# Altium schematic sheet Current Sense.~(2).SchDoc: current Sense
size 431 x 279 mm; Date: Not shown in title block; ApprovedBy: Not shown in title block; CheckedBy: Not shown in title block; Author: Not shown in title block; CompanyName: Not shown in title block; Engineer: Not shown in title block; Organization: Not shown in title block; Address1: Not shown in title block; Address2: Not shown in title block; Address3: Not shown in title block; Address4: Not shown in title block; DocumentNumber: 3; Revision: Use project parameter SCH_Rev; SheetNumber: 3; SheetTotal: 7; PageSetup: Record=PageOptions|CenterHorizontal=True|CenterVertical=True|PrintScale=1.00|XCorrection=1.00|YCorrection=1.00|PrintKind=0|BorderSize=5000000|LeftOffset=0|BottomOffset=0|Orientation=2|PaperLength=1000|PaperWidth=1000|Scale=100|PaperSource=15|PrintQuality=600|MediaType=1|DitherType=10|PaperKind=Letter|PrintScaleMode=1
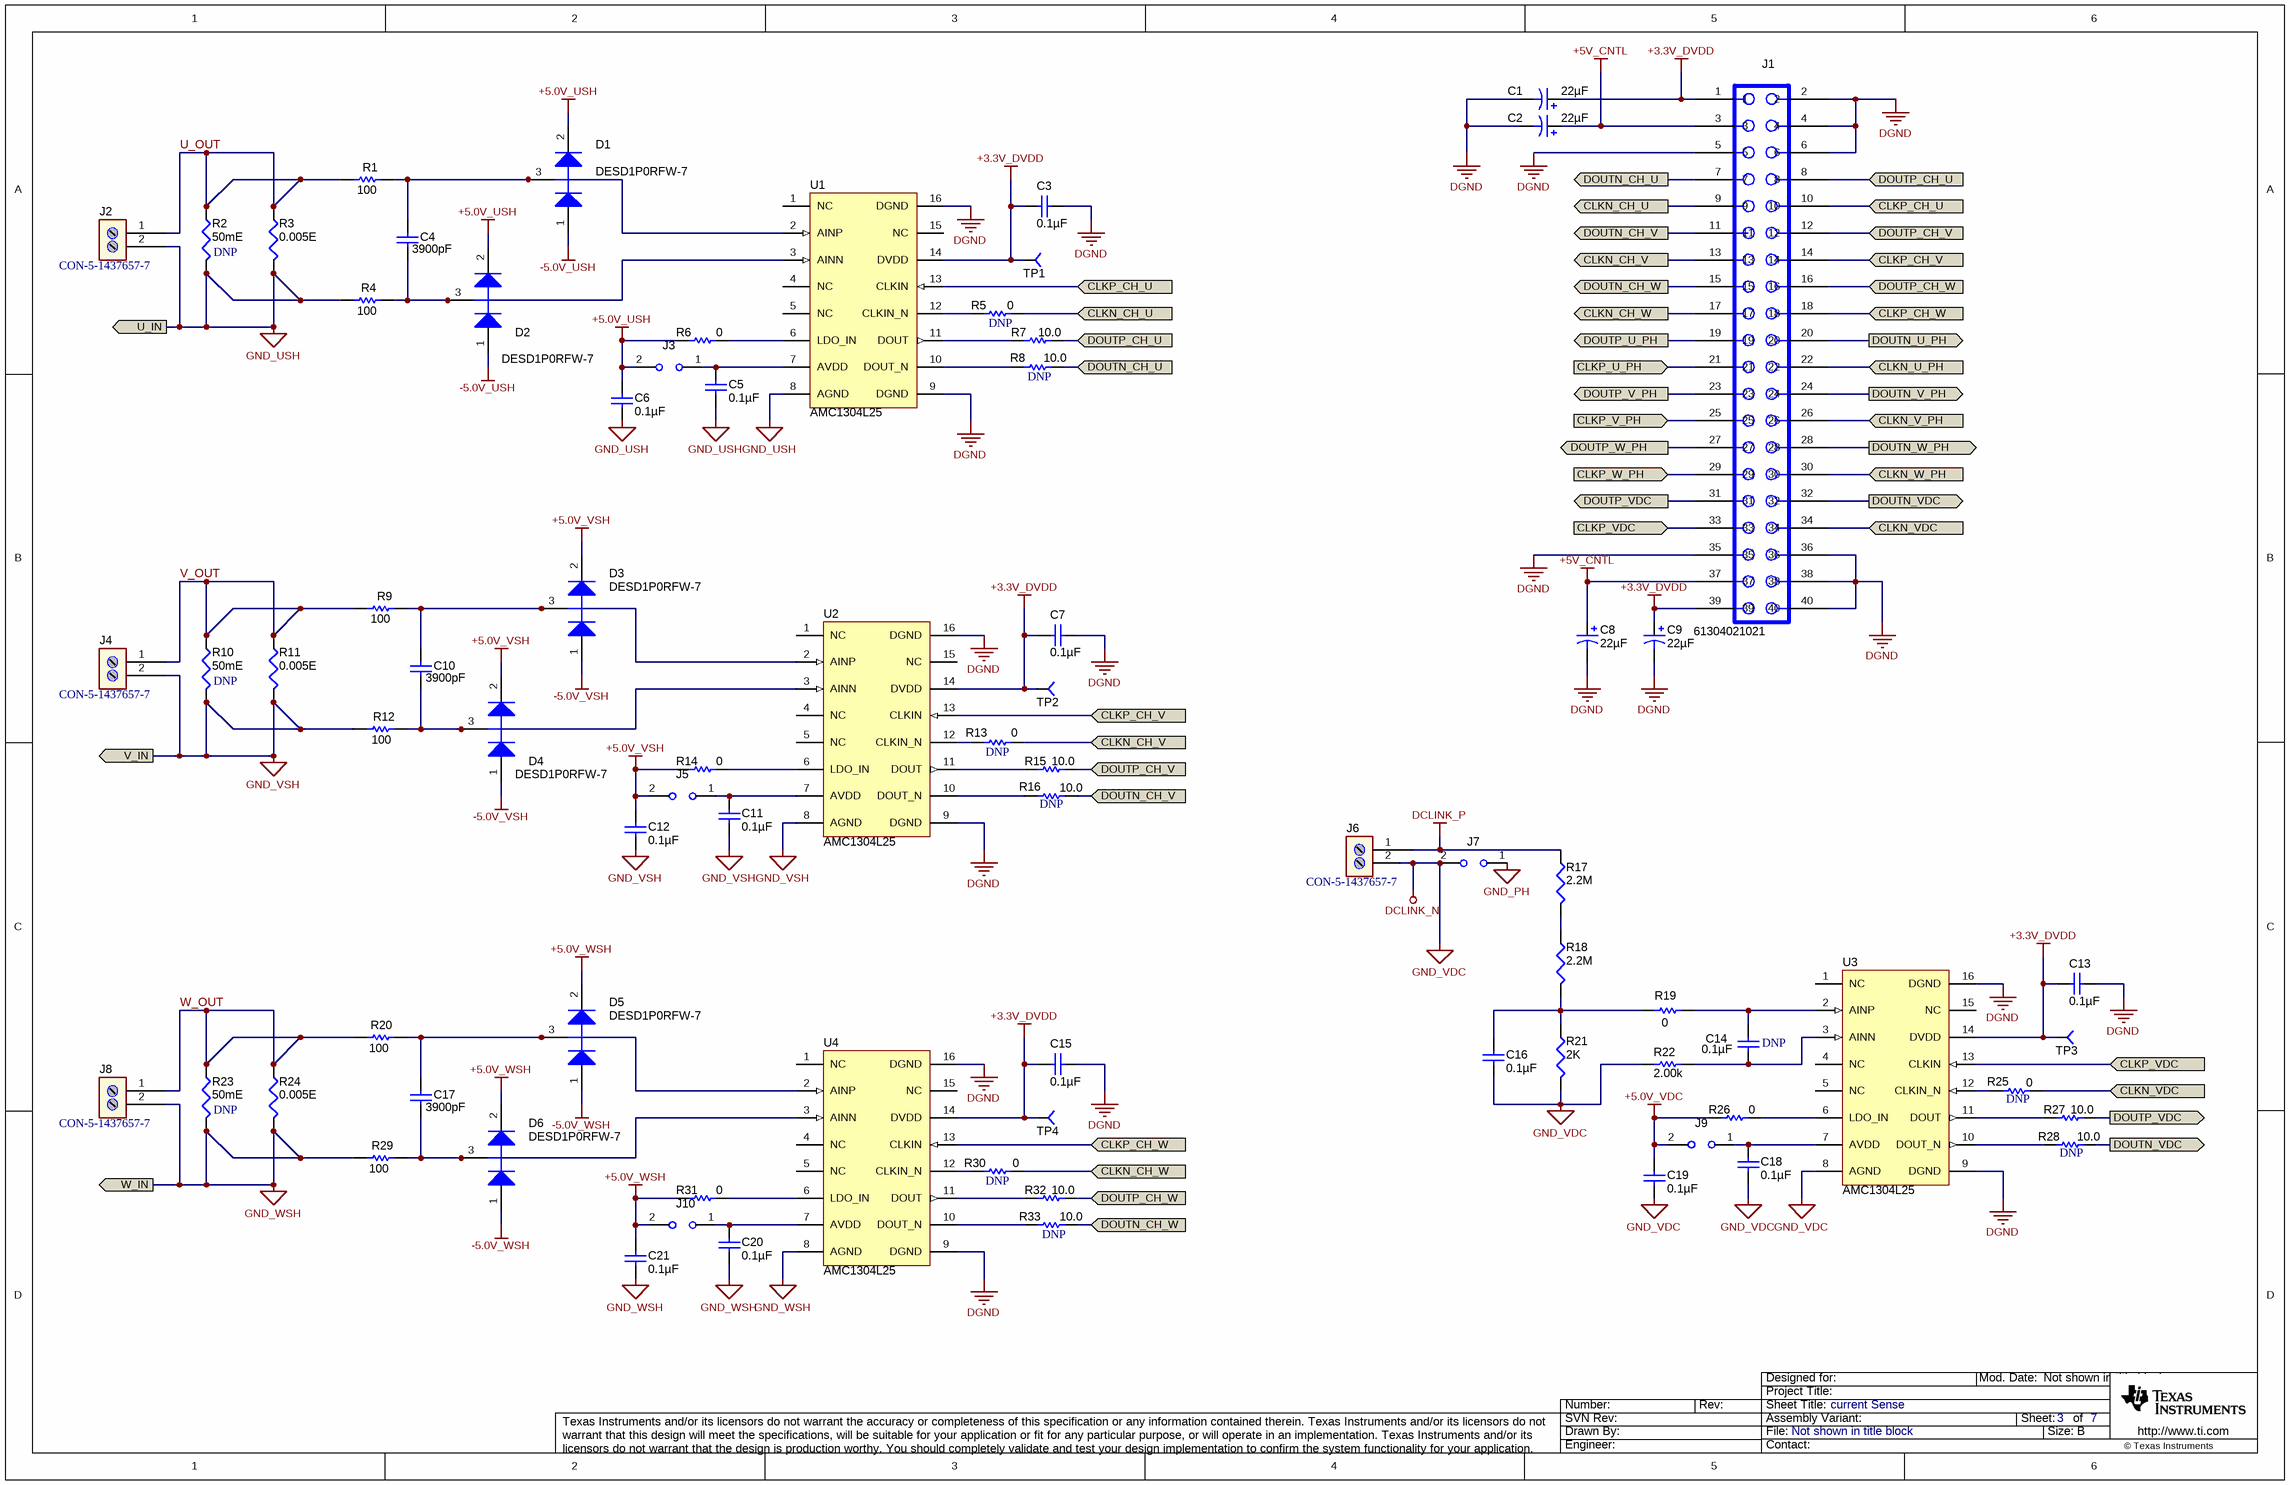
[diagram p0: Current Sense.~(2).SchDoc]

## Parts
C1  ValueDisplayed: 22µF  [SM_RADIAL_5MM]  (hidden comment: UUD1E220MCL1GS)
C2  ValueDisplayed: 22µF  [SM_RADIAL_5MM]  (hidden comment: UUD1E220MCL1GS)
C3  ValueDisplayed: 0.1µF  [0603]
C4  ValueDisplayed: 3900pF  [0603]  (hidden comment: C1608C0G1E392J)
C5  ValueDisplayed: 0.1µF  [0603]
C6  ValueDisplayed: 0.1µF  [0603]
C7  ValueDisplayed: 0.1µF  [0603]
C8  ValueDisplayed: 22µF  [SM_RADIAL_5MM]  (hidden comment: UUD1E220MCL1GS)
C9  ValueDisplayed: 22µF  [SM_RADIAL_5MM]  (hidden comment: UUD1E220MCL1GS)
C10  ValueDisplayed: 3900pF  [0603]  (hidden comment: C1608C0G1E392J)
C11  ValueDisplayed: 0.1µF  [0603]
C12  ValueDisplayed: 0.1µF  [0603]
C13  ValueDisplayed: 0.1µF  [0603]
C14  ValueDisplayed: 0.1µF  Not mounted: DNP  [0603]
C15  ValueDisplayed: 0.1µF  [0603]
C16  ValueDisplayed: 0.1µF  [0603]
C17  ValueDisplayed: 3900pF  [0603]  (hidden comment: C1608C0G1E392J)
C18  ValueDisplayed: 0.1µF  [0603]
C19  ValueDisplayed: 0.1µF  [0603]
C20  ValueDisplayed: 0.1µF  [0603]
C21  ValueDisplayed: 0.1µF  [0603]
D1  value DESD1P0RFW-7  [SOT-323]
D2  value DESD1P0RFW-7  [SOT-323]
D3  DESD1P0RFW-7  [SOT-323]
D4  DESD1P0RFW-7  [SOT-323]
D5  DESD1P0RFW-7  [SOT-323]
D6  DESD1P0RFW-7  [SOT-323]
J1  61304021021  [CONN_61304021021]
J2  CON-5-1437657-7  [5-1437657-7]
J3  (no value)  [HDR100_1X2]
J4  CON-5-1437657-7  [5-1437657-7]
J5  (no value)  [HDR100_1X2]
J6  CON-5-1437657-7  [5-1437657-7]
J7  (no value)  [HDR100_1X2]
J8  CON-5-1437657-7  [5-1437657-7]
J9  (no value)  [HDR100_1X2]
J10  (no value)  [HDR100_1X2]
R1  value 100  [0603]  (hidden comment: RC0603FR-07100RL)
R2  value 50mE  Not mounted: DNP  [R_TO-247]  (hidden comment: PBH-R050-F1-0.5)
R3  value 0.005E  [PWR4413D-R050F]  (hidden comment: OAR5R005FLF)
R4  value 100  [0603]  (hidden comment: RC0603FR-07100RL)
R5  value 0  Not mounted: DNP  [0603]
R6  value 0  [0603]
R7  value 10.0  [0603]
R8  value 10.0  Not mounted: DNP  [0603]
R9  value 100  [0603]  (hidden comment: RC0603FR-07100RL)
R10  value 50mE  Not mounted: DNP  [R_TO-247]  (hidden comment: PBH-R050-F1-0.5)
R11  value 0.005E  [PWR4413D-R050F]  (hidden comment: OAR5R005FLF)
R12  value 100  [0603]  (hidden comment: RC0603FR-07100RL)
R13  value 0  Not mounted: DNP  [0603]
R14  value 0  [0603]
R15  value 10.0  [0603]
R16  value 10.0  Not mounted: DNP  [0603]
R17  value 2.2M  [1210M]
R18  value 2.2M  [1210M]
R19  value 0  [0603]  (hidden comment: CRCW06030000Z0EA)
R20  value 100  [0603]  (hidden comment: RC0603FR-07100RL)
R21  value 2K  [1210M]
R22  value 2.00k  [0603]  (hidden comment: RT0603DRE072KL)
R23  value 50mE  Not mounted: DNP  [R_TO-247]  (hidden comment: PBH-R050-F1-0.5)
R24  value 0.005E  [PWR4413D-R050F]  (hidden comment: OAR5R005FLF)
R25  value 0  Not mounted: DNP  [0603]
R26  value 0  [0603]
R27  value 10.0  [0603]
R28  value 10.0  Not mounted: DNP  [0603]
R29  value 100  [0603]  (hidden comment: RC0603FR-07100RL)
R30  value 0  Not mounted: DNP  [0603]
R31  value 0  [0603]
R32  value 10.0  [0603]
R33  value 10.0  Not mounted: DNP  [0603]
TP1  (no value)  [TP-040_RND]
TP2  (no value)  [TP-040_RND]
TP3  (no value)  [TP-040_RND]
TP4  (no value)  [TP-040_RND]
U1  AMC1304L25  [DW0016A_N]
U2  AMC1304L25  [DW0016A_N]
U3  AMC1304L25  [DW0016A_N]
U4  AMC1304L25  [DW0016A_N]

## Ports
CLKN_CH_U, CLKN_CH_V, CLKN_CH_W, CLKN_U_PH (in), CLKN_V_PH (in), CLKN_VDC (in), CLKN_W_PH (in), CLKP_CH_U, CLKP_CH_V, CLKP_CH_W, CLKP_U_PH (in), CLKP_V_PH (in), CLKP_VDC (in), CLKP_W_PH (in), DOUTN_CH_U, DOUTN_CH_V, DOUTN_CH_W, DOUTN_U_PH (out), DOUTN_V_PH (out), DOUTN_VDC (out), DOUTN_W_PH (out), DOUTP_CH_U, DOUTP_CH_V, DOUTP_CH_W, DOUTP_U_PH (out), DOUTP_V_PH (out), DOUTP_VDC (out), DOUTP_W_PH (out), U_IN (out), V_IN (out), W_IN (out)

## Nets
+3.3V_DVDD: C1.1(+) C3.2 C7.2 C9.1(+) C13.2 C15.2 J1.1 J1.39 TP1.1 TP2.1 TP3.1 TP4.1 U1.14(DVDD) U2.14(DVDD) U3.14(DVDD) U4.14(DVDD)
+5.0V_USH: C6.1 D1.2(K) D2.2(K) J3.2 R6.1
+5.0V_VDC: C19.1 J9.2 R26.1
+5.0V_VSH: C12.1 D3.2(K) D4.2(K) J5.2 R14.1
+5.0V_WSH: C21.1 D5.2(K) D6.2(K) J10.2 R31.1
+5V_CNTL: C2.1(+) C8.1(+) J1.3 J1.37
-5.0V_USH: D1.1(A) D2.1(A)
-5.0V_VSH: D3.1(A) D4.1(A)
-5.0V_WSH: D5.1(A) D6.1(A)
DCLINK_N: C16.1 C18.2 C19.2 J6.2 J7.2 R21.2 R22.1 U3.8(AGND)  [also labelled GND_VDC]
DCLINK_P: J6.1 R17.1
DGND: C1.2(-) C2.2(-) C3.1 C7.1 C8.2(-) C9.2(-) C13.1 C15.1 J1.2 J1.4 J1.5 J1.6 J1.35 J1.36 J1.38 J1.40 U1.9(DGND) U1.16(DGND) U2.9(DGND) U2.16(DGND) U3.9(DGND) U3.16(DGND) U4.9(DGND) U4.16(DGND)
GND_PH: J7.1
GND_USH: C5.2 C6.2 J2.2 R2.2 R3.2 R4.1 U1.8(AGND) ; port U_IN
GND_VSH: C11.2 C12.2 J4.2 R10.2 R11.2 R12.1 U2.8(AGND) ; port V_IN
GND_WSH: C20.2 C21.2 J8.2 R23.2 R24.2 R29.1 U4.8(AGND) ; port W_IN
CLKN_CH_U: J1.9 R5.2 ; port CLKN_CH_U
CLKN_CH_V: J1.13 R13.2 ; port CLKN_CH_V
CLKN_CH_W: J1.17 R30.2 ; port CLKN_CH_W
CLKN_U_PH: J1.22 ; port CLKN_U_PH
CLKN_V_PH: J1.26 ; port CLKN_V_PH
CLKN_VDC: J1.34 R25.2 ; port CLKN_VDC
CLKN_W_PH: J1.30 ; port CLKN_W_PH
CLKP_CH_U: J1.10 U1.13(CLKIN) ; port CLKP_CH_U
CLKP_CH_V: J1.14 U2.13(CLKIN) ; port CLKP_CH_V
CLKP_CH_W: J1.18 U4.13(CLKIN) ; port CLKP_CH_W
CLKP_U_PH: J1.21 ; port CLKP_U_PH
CLKP_V_PH: J1.25 ; port CLKP_V_PH
CLKP_VDC: J1.33 U3.13(CLKIN) ; port CLKP_VDC
CLKP_W_PH: J1.29 ; port CLKP_W_PH
DOUTN_CH_U: J1.7 R8.2 ; port DOUTN_CH_U
DOUTN_CH_V: J1.11 R16.2 ; port DOUTN_CH_V
DOUTN_CH_W: J1.15 R33.2 ; port DOUTN_CH_W
DOUTN_U_PH: J1.20 ; port DOUTN_U_PH
DOUTN_V_PH: J1.24 ; port DOUTN_V_PH
DOUTN_VDC: J1.32 R28.2 ; port DOUTN_VDC
DOUTN_W_PH: J1.28 ; port DOUTN_W_PH
DOUTP_CH_U: J1.8 R7.2 ; port DOUTP_CH_U
DOUTP_CH_V: J1.12 R15.2 ; port DOUTP_CH_V
DOUTP_CH_W: J1.16 R32.2 ; port DOUTP_CH_W
DOUTP_U_PH: J1.19 ; port DOUTP_U_PH
DOUTP_V_PH: J1.23 ; port DOUTP_V_PH
DOUTP_VDC: J1.31 R27.2 ; port DOUTP_VDC
DOUTP_W_PH: J1.27 ; port DOUTP_W_PH
U_OUT: J2.1 R1.1 R2.1 R3.1
V_OUT: J4.1 R9.1 R10.1 R11.1
W_OUT: J8.1 R20.1 R23.1 R24.1
NetC4_1: C4.1 D1.3(C) R1.2 U1.2(AINP)
NetC4_2: C4.2 D2.3(C) R4.2 U1.3(AINN)
NetC5_1: C5.1 J3.1 U1.7(AVDD)
NetC10_1: C10.1 D3.3(C) R9.2 U2.2(AINP)
NetC10_2: C10.2 D4.3(C) R12.2 U2.3(AINN)
NetC11_1: C11.1 J5.1 U2.7(AVDD)
NetC14_1: C14.1 R19.2 U3.2(AINP)
NetC14_2: C14.2 R22.2 U3.3(AINN)
NetC16_2: C16.2 R18.2 R19.1 R21.1
NetC17_1: C17.1 D5.3(C) R20.2 U4.2(AINP)
NetC17_2: C17.2 D6.3(C) R29.2 U4.3(AINN)
NetC18_1: C18.1 J9.1 U3.7(AVDD)
NetC20_1: C20.1 J10.1 U4.7(AVDD)
NetR5_1: R5.1 U1.12(CLKIN_N)
NetR6_2: R6.2 U1.6(LDO_IN)
NetR7_1: R7.1 U1.11(DOUT)
NetR8_1: R8.1 U1.10(DOUT_N)
NetR13_1: R13.1 U2.12(CLKIN_N)
NetR14_2: R14.2 U2.6(LDO_IN)
NetR15_1: R15.1 U2.11(DOUT)
NetR16_1: R16.1 U2.10(DOUT_N)
NetR17_2: R17.2 R18.1
NetR25_1: R25.1 U3.12(CLKIN_N)
NetR26_2: R26.2 U3.6(LDO_IN)
NetR27_1: R27.1 U3.11(DOUT)
NetR28_1: R28.1 U3.10(DOUT_N)
NetR30_1: R30.1 U4.12(CLKIN_N)
NetR31_2: R31.2 U4.6(LDO_IN)
NetR32_1: R32.1 U4.11(DOUT)
NetR33_1: R33.1 U4.10(DOUT_N)

Not connected (* = marked no-connect by the designer): U1 1(NC) 4(NC) 5(NC) 15(NC); U2 1(NC) 4(NC) 5(NC) 15(NC); U3 1(NC) 4(NC) 5(NC) 15(NC); U4 1(NC) 4(NC) 5(NC) 15(NC)

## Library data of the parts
C1 C2 C8 C9 = UUD1E220MCL1GS: CAP, AL, 22uF, 25V, +/-20%, 0.76 ohm, SMD; Manufacturer: Nichicon; Polarized: Y; CompType: Capacitor; U/M: EA; Cap_F: 0.000022; Tolerance_%: 20; VDC_V: 25; ESR_Ohm: 0.76; IRMS_A: 0.15; TaMin_C: -55; TaMax_C: 105; Cap_Case: 5x5.8
C3 C7 C13 C15 = 06033C104JAT2A: CAP, CERM, 0.1uF, 25V, +/-5%, X7R, 0603; Manufacturer: AVX; Polarized: N; CompType: Capacitor; U/M: EA; Cap_F: 0.0000001; Tolerance_%: 5; ESR_Ohm: 0.05; Value1: 0.05 ohm; VDC_V: 25; TaMin_C: -55; TaMax_C: 125
C4 C10 C17 = C1608C0G1E392J: CAP, CERM, 3900pF, 25V, +/-5%, C0G/NP0, 0603; Manufacturer: TDK; Polarized: N; CompType: Capacitor; U/M: EA; Cap_F: 0.0000000039; Tolerance_%: 5; Value1: Unknown; VDC_V: 25; TaMin_C: -55; TaMax_C: 125
C5 C6 C11 C12 C14 C16 C18-C21 = C0603C104K5RACTU: CAP, CERM, 0.1uF, 50V, +/-10%, X7R, 0603; Manufacturer: Kemet; Polarized: N; CompType: Capacitor; U/M: EA; Cap_F: 0.0000001; Tolerance_%: 10; Value1: Unknown; VDC_V: 50; TaMin_C: -55; TaMax_C: 125
D1 D2 = BAV99WT1G: Diode, P-N, 70V, 0.2A, SOT-323; Manufacturer: Diodes Inc
D3-D6 = BAV99WT1G: Diode, P-N, 70V, 0.2A, SOT-323; Manufacturer: Diodes Inc; Value: DNP
J1 = CONN_61304021021: Connector, Right Angle 2x20 pin, 100mil spacing; Manufacturer: WURTH ELEKTRONIK; area: 1.262.250
J2 J4 J6 J8 = CON-5-1437657-7: Terminal Block, 4x1, 2.54mm, TH; Manufacturer: On Shore Technology Inc; PartNumber: OSTVN02A150; SymbolCreator: x0120606
J3 J5 J7 J9 J10 = JUMPER_2X100MIL: Header, Male 2-pin, 100mil spacing,; Manufacturer: Sullins; PartNumber: PEC02SAAN; area: 20000; Value: PEC02SAAN
R1 R4 R9 R12 R20 R29 = RC0603FR-07100RL: RES, 100 ohm, 1%, 0.1W, 0603; Manufacturer: Yageo America; CompType: Resistor; Value_Code: 100R; Tolerance_%: 1; Power_W: 0.1; VDC_V: 150; TempCo: 200 ppm/C; EIA_Code: E96; U/M: EA
R2 R10 R23 = PBH-R050-F1-0.5: RES 50mOHM 3W .5% TO-247 TH; Manufacturer: ISOTEK; CompType: Resistor
R3 R11 R24 = RES_PWR4413DR050F: RES METAL .005 OHM 5W 1% RADIAL; Manufacturer: TT Electronics/IRC; CompType: Resistor
R5 R6 R13 R14 R19 R25 R26 R30 R31 = CRCW06030000Z0EA: RES, 0 ohm, 5%, 0.1W, 0603; Manufacturer: Vishay-Dale; CompType: Resistor; Value_Code: 0000; Tolerance_%: 5; Power_W: 0.1; VDC_V: 75; TempCo: 200 ppm/C; EIA_Code: E24; U/M: EA
R7 R8 R15 R16 R27 R28 R32 R33 = CRCW060310R0FKEA: RES, 10.0 ohm, 1%, 0.1W, 0603; Manufacturer: Vishay-Dale; CompType: Resistor; Res_ohm: 10; Value_Code: 10R0; Tolerance_%: 1; Power_W: 0.1; VDC_V: 75; TempCo: 100 ppm/C; EIA_Code: E96; U/M: EA
R17 R18 = RES_KTR25JZPF2204: RES 2.2M OHM 1/3W 1% 1210; Manufacturer: Rohm Semiconductor; CompType: Resistor
R21 = RES_KTR25JZPF2001: RES 2K OHM 1/3W 1% 1210; Manufacturer: Rohm Semiconductor; CompType: Resistor
R22 = RT0603DRE072KL: RES, 2.00k ohm, 0.5%, 0.1W, 0603; Manufacturer: Yageo America; CompType: Resistor; Res_ohm: 2000; Value_Code: 2k00; Tolerance_%: 0.5; Power_W: 0.1; VDC_V: 75; TempCo: 50 ppm/C; EIA_Code: E192; U/M: EA
TP1-TP4 = TP-040_RND: Test Point, O.040 Hole; Manufacturer: STD; Value: STD
U1 U2 U4 = AMC1304L25: 20 MHz, Isolated Delta-Sigma Modulator, LVDS interface:; PartNumber: AMC1304M05; Alternate Manufacturer: None; Manufacturer: Texas Instruments; SymbolCreator: x0120606; CompType: IC
U3 = AMC1304L25: 20 MHz, Isolated Delta-Sigma Modulator, LVDS interface:; PartNumber: AMC1304M25; Alternate Manufacturer: None; Manufacturer: Texas Instruments; SymbolCreator: x0120606; CompType: IC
